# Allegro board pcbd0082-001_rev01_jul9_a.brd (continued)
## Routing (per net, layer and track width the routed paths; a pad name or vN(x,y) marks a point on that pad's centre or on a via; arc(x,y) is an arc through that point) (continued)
VDD_CORE_EN: length 29.2
  TOP w0.127: v3(30.09,33.65) 30.05,33.65 29.63,33.23 28.96,33.23 28.69,33.51
  TOP w0.147: 28.69,33.51 28.18,34.02 28.18,38 28.31,38.12 28.31,40.54 TP58.1 ; U10.6 30.73,20.47 30.66,20.4 30.2,20.4 v4(29.49,21.11)
  02_GND w0.127: v3(30.09,33.65) 30.46,33.28 U2.G13
  07_SIG w0.121: v3(30.09,33.65) 29.69,33.26 29.69,32.65 29.2,32.15 29.2,31.27 28.05,30.12 28.05,28.22 28.31,27.96 28.31,26.7 29.07,25.95 29.07,24.48 28.44,23.85 28.44,21.99 29.32,21.11 v4(29.49,21.11)
VDD_CORE_PGOOD: length 44.3
  TOP w0.132: U1.P28 v2(45.9,37.28) ; U1.N28 v2(45.9,36.28)
  TOP w0.147: U10.40 31.47,23.67 v4(31.36,23.56) 31.14,23.77 R87.1
  TOP w0.254: TP59.1 29.71,12.79 v5(29.83,12.91)
  02_GND w0.127: U2.E2 37.58,32.28 37.86,32 38.06,32 v3(38.6,31.47)
  07_SIG w0.121: v4(31.36,23.56) 33.17,23.56 34.22,24.6 34.22,25.23 34.59,25.6 34.59,28.05 34.64,28.1 34.64,29.73 35.29,30.38 37.58,30.38 38.6,31.39 v3(38.6,31.47) 38.99,31.86 45.29,31.86 46.47,33.04 46.47,35.71 45.9,36.28 v2(45.9,36.28) v2(45.9,37.28)
  08_SIG w0.121: v4(31.36,23.56) 31.36,20.85 30.69,20.19 30.69,17.37 30.59,17.27 30.59,13.68 v5(29.83,12.91)
VDDA_DDR0_32A: length 10
  TOP w0.254: v2(64.9,47.28) U1.AC10 ; v2(64.9,46.28) U1.AB10
  BOTTOM w0.254: v1(67.81,50.19) 67.4,49.79 67.4,48.77 66.41,47.78 C116.1 v2(64.9,47.28) 64.4,47.78 C187.1 ; U1.AC10 v2(64.9,46.28) U1.AB10 ; C44.1 v2(56.9,38.28)
  BOTTOM w0.508: L7.2 56.96,38.22 v2(56.9,38.28)
VDDA_DDR0_32B: length 7.1
  TOP w0.254: U1.Y10 v2(64.9,44.28) U1.AA10
  07_SIG w0.203: v2(64.9,44.28) 64.95,44.28 65.45,43.78 65.45,42.51 66.12,41.84 67.27,41.84 67.81,41.3 v8(67.9,41.28)
  BOTTOM w0.254: v2(64.9,44.28) U1.AA10
VDDA_PCIE0: length 13.7
  TOP w0.254: v2(62.9,50.28) U1.AF12 ; v2(60.9,50.28) U1.AF14 ; v2(61.9,50.28) U1.AF13
  BOTTOM w0.254: v2(64.9,54.28) 64.85,54.34 C279.1 64.85,55.48 66.28,56.92 67.3,56.92 v1(67.68,57.3) ; v2(60.9,50.28) C90.1 ; C170.1 63.4,49.78 C37.1 v2(62.9,50.28) C169.1 ; v2(61.9,50.28) C89.1 ; v2(63.9,53.28) 63.9,53.04 C278.1
  BOTTOM w0.381: v4(56.9,50.28) 56.9,50.33 56.97,50.4 56.97,50.56 57.69,51.28 v4(57.9,51.28)
VDDA_PLL: length 10.5
  TOP w0.254: v2(64.9,41.28) U1.U10 ; U1.M27 v2(46.9,35.28) ; U1.N27 v2(46.9,36.28) ; U1.AC18 v2(55.9,47.28) ; U1.K27 v2(46.9,33.28)
  BOTTOM w0.254: v2(46.9,36.28) C27.1 ; v2(46.9,33.28) C25.1 ; v2(55.9,47.28) C28.1 ; v2(46.9,35.28) C26.1 ; v1(42.91,28.22) 42.28,28.85 42.28,29.61 41.77,30.12 v4(40.75,30.12) ; v2(64.9,41.28) C29.1
  vias: v4(40.75,31.27)
VDDA_SERDES: length 23.3
  TOP w0.254: U1.AE24 v2(49.9,49.28) ; U1.AE23 v2(50.9,49.28) ; U1.AF23 v2(50.9,50.28) ; U1.AF22 v2(51.9,50.28) ; U1.AE22 v2(51.9,49.28)
  BOTTOM w0.203: v4(57.9,47.28) 58.27,46.91 58.35,46.91 58.5,46.77 59.1,46.77 59.38,46.48 59.38,46.42 59.42,46.38 v1(59.42,40.16)
  BOTTOM w0.254: v2(49.9,49.28) U1.AE24 C92.1 ; C94.1 51.41,47.78 51.4,47.78 ; v2(50.9,49.28) 51.4,48.78 51.4,47.78 ; C172.1 C93.1 51.4,47.78 ; U1.AF22 v2(51.9,49.28) ; v2(50.9,50.28) C40.1
  BOTTOM w0.457: v2(50.9,50.28) 50.9,50.33 50.79,50.44 50.79,51.84 C281.1
  BOTTOM w0.508: C280.1 51.93,53.24 51.23,52.53 C281.1 ; v4(57.9,47.28) v2(57.9,48.28)
VDDA_TS0: length 8.1
  TOP w0.254: U1.M32 v2(41.9,35.28)
  BOTTOM w0.127: L14.1 40.93,35.37 40.07,35.37 39.83,35.12 39.83,34.74 39.68,34.59 38.24,34.59 v1(37.74,34.09)
  BOTTOM w0.254: v2(41.9,35.28) 41.02,35.28 L14.1 ; v2(41.9,35.28) U1.M32 C86.1 ; v2(41.9,35.28) 42.4,34.78 C74.1
VDDAH_PCIE0: length 17.4
  TOP w0.254: v2(58.9,50.28) U1.AF16
  BOTTOM w0.254: L1.2 67.94,55.13 68.57,54.51 68.57,54 v1(67.93,53.36) 67.52,53.78 63.69,53.78 63.4,53.49 63.4,53.09 63.09,52.78 61.7,52.78 61.4,53.08 61.4,53.45 61.39,53.46 61.39,53.49 61.1,53.78 59.69,53.78 59.4,53.48 C39.1 C38.1 C91.1 v2(58.9,50.28) C30.1
VDDAH_SERDES: length 18.4
  TOP w0.254: U1.AF20 v2(53.9,50.28) ; U1.AF21 v2(52.9,50.28)
  BOTTOM w0.254: v2(53.9,50.28) U1.AF21 53.4,49.78 v2(52.9,50.28) ; v2(53.9,50.28) C102.1 C43.1 ; v2(53.9,50.28) 54.31,50.7 55.11,50.7 55.4,50.99 C101.1 C42.1 C41.1 55.4,54.48 55.1,54.78 55.09,54.78 54.72,55.14 54.72,56.28 54.09,56.92 53.71,56.92 53.2,56.41 52.77,56.41 52.44,56.74 52.44,56.74 52.39,56.79 51.29,56.79 v1(50.91,56.41) 50.33,56.99 50.33,57.1 L15.2
VDDQ_VTT_EN: length 70.5
  TOP w0.127: v3(33.87,33.55) 33.48,33.95 32.58,33.95 U2.H12
  TOP w0.147: TP65.1 88,21.07 v4(87.36,20.43) 86.85,19.92 86.85,19.2 86.45,18.79 U3.16 85.6,19.32 85.46,19.45 85.33,19.45 85.2,19.32 U3.17
  03_SIG w0.121: v5(82.66,23.14) 78.35,23.14 73.77,27.71 45.33,27.71 44.82,28.22 39.99,28.22 37.07,31.14 35.42,31.14 34.91,31.65 34.91,32.93 34.66,33.18 34.27,33.18 33.9,33.55 v3(33.87,33.55)
  07_SIG w0.121: v4(87.36,20.43) 86.95,20.02 86.04,20.02 85.98,19.96 84.32,19.96 83.3,20.98 83.3,22.5 v5(82.66,23.14)
VDDQ_VTT_PGOOD: length 59.8
  TOP w0.127: U2.E1 38.36,32.73 38.99,32.73 v3(39.41,33.15)
  TOP w0.147: U3.20 84,19.52 84.57,20.09 v4(84.57,20.43) 84.66,20.43 85.08,20.85 85.08,21.74 85.46,22.12 86.09,22.12 86.47,22.5 TP60.1
  03_SIG w0.121: v3(39.41,33.15) 40.78,31.77 41.01,31.77 42.15,30.63 44.71,30.63 44.73,30.65 45.07,30.65 45.09,30.63 45.33,30.63 46.2,29.76 72.23,29.76 77.58,24.41 v5(82.66,24.41)
  07_SIG w0.121: v5(82.66,24.41) 83.81,23.26 83.81,21.19 v4(84.57,20.43)
3N2284: length 4.1
  TOP w0.147: U14.1 35.05,49.82 34.79,49.55 v1(33.01,49.55) 32.3,49.55 32.16,49.7 R268.2
3N2285: length 1.2
  TOP w0.147: v4(36.44,56.12) 36.55,56 U14.11
3N2286: length 2.5
  TOP w0.147: U14.20 33.79,51.22 33.39,50.82 v1(33.08,50.82) R15.2
3N2287: length 3.5
  TOP w0.147: v1(38.56,56.12) R14.2 37.43,56.09 U14.10
3N2290: length 1.6
  TOP w0.147: v4(38.68,51.33) 37.79,52.22 U14.7
3N2291: length 1.4
  TOP w0.147: v4(38.68,52.47) 38.21,52.47 37.96,52.72 U14.8
3N2301: length 2.7
  TOP w0.147: U14.5 37.81,50.84 37.81,49.92 R135.1
  vias: v4(38.68,49.12)
3N2302: length 2.2
  TOP w0.147: U14.6 37.69,51.72 38.09,51.33 38.09,50.79 v4(38.68,50.19)
3N2521: length 11.3
  TOP w0.147: U15.7 v4(24.68,40.66) 25.13,41.12 R21.2
  BOTTOM w0.147: v1(25.95,31.95) 25.72,31.95 25.13,32.54 U7.7 25.13,36.09 24.52,36.7 24.52,40.51 v4(24.68,40.66)
6N3961: length 5.4
  TOP w0.132: v2(67.9,37.28) U1.P7
  BOTTOM w0.147: R124.2 69.96,34.83 R272.1 69.08,35.72 v1(69.08,36.85) 68.65,37.28 v2(67.9,37.28)
6N3963: length 2.9
  TOP w0.132: v2(65.9,37.28) U1.P9
  BOTTOM w0.147: v1(64.9,38.28) 65.48,37.58 65.61,37.58 v2(65.9,37.28) R310.1
6N4748: length 2.8
  TOP w0.147: R7.2 R8.2 79.41,30.67 v1(78.55,30.67) C105.1
9N1879: length 2.5
  TOP w0.147: U2.A4 36.41,29.64 v3(35.85,29.08)
  BOTTOM w0.147: v3(35.85,29.08) 35.67,29.26 R264.1
9N2032: length 3.7
  TOP w0.147: v7(27.67,24.66) 27.6,24.74 U12.15
  BOTTOM w0.147: v7(27.67,24.66) 27.04,25.3 27.04,26.44 26.4,27.07 R59.1
9N2141: length 8.9
  TOP w0.147: DS1.2 10.45,57.99 v5(11.04,58.57) v1(11.04,59.84)
  BOTTOM w0.147: R277.2 11.04,57.39 v5(11.04,58.57)
9N2152: length 8.4
  TOP w0.147: DS1.3 11.95,57.68 12.18,57.91 v6(12.18,58.57)
  BOTTOM w0.147: v6(12.18,58.57) 12.18,57.64 R276.2
10N2223: length 3.1
  BOTTOM w0.147: v1(45.2,17.42) 45.71,17.93 46.09,17.93 46.68,18.53 R117.1
  BOTTOM w0.508: C46.1 R117.1
10N2224: length 5.6
  BOTTOM w0.147: v1(65.38,23.36) 65.38,22.24 64.94,21.8 64.94,21.18 65.83,20.29 65.83,20.16 66.28,19.7 C47.1
  BOTTOM w0.508: C47.1 R116.1
10N2225: length 9.1
  BOTTOM w0.132: U5.3 50.13,21.79 50.69,22.35 50.69,23.88 50.46,24.1 50.46,24.22 50.41,24.28 50.41,25.55 50.11,25.85 49.72,25.85 49.33,26.23 49.33,26.46 49.08,26.72 47.64,26.72 v1(46.98,26.06)
10N2227: length 3.1
  BOTTOM w0.147: v1(70.85,23.4) 70.85,23.32 70.99,23.19 70.99,22.38 70.72,22.11 70.34,22.11 69.73,21.51 U6.3
10N2228: length 3.8
  BOTTOM w0.147: C32.2 73.81,24.06 74.03,24.28 v1(75.17,24.28) 76.02,24.28 R119.1
10N2229: length 7.8
  BOTTOM w0.147: v1(75.17,25.68) 74.22,24.72 72.72,24.72 72.46,24.47 72.46,24.22 72.21,23.97 C32.1 72.12,23.26 71.26,22.41 71.26,22.26 70.84,21.84 70.45,21.84 70.23,21.62 U6.4
10N2230: length 9
  BOTTOM w0.147: v1(65.77,27.17) 65.41,26.81 65.41,26.05 65.65,25.8 66.15,25.8 66.4,25.56 R170.2 66.41,24.77 66.41,23.01 67.3,22.12 67.3,20.22 67.58,19.93 U6.39
10N2232: length 7.8
  TOP w0.147: v1(46.22,21.36) 46.34,21.49 46.85,21.49 47.49,22.12 v5(51.13,22.12)
  BOTTOM w0.147: C33.1 51.35,22.34 v5(51.13,22.12) 50.63,21.63 U5.4
10N2233: length 10.9
  BOTTOM w0.147: R118.1 C33.2 52.95,23.39 52.34,24 52.34,26.47 51.97,26.84 49.72,26.84 49.34,27.22 49.34,27.47 49.08,27.72 47.5,27.72 47.1,27.33 v1(46.98,27.33)
10N2235: length 7.4
  BOTTOM w0.147: R169.2 v1(44.82,22.12) 45.45,22.12 46.22,22.88 47.1,22.88 47.61,22.38 47.61,20.22 47.89,19.93 U5.39
10N2253: length 3.1
  BOTTOM w0.147: v1(67,23.26) 67.55,22.72 R126.2 68.06,22.63 68.22,22.47 68.22,21.83 68.73,21.32 U6.1
10N2256: length 3.3
  BOTTOM w0.147: U5.1 49.13,21.32 48.46,21.99 R74.2 48.16,22.72 v1(47.36,23.52)
10N2259: length 9.6
  BOTTOM w0.147: v1(58.79,21.49) 58.44,21.83 58.44,22.89 57.93,23.41 R118.2 55.11,22.63 52.65,22.63 52.53,22.5 52.53,21.87 52.13,21.47 U5.7
10N2262: length 8
  BOTTOM w0.147: R119.2 77.37,23.01 v1(75.17,23.01) 74.79,22.63 72.3,22.63 72.17,22.5 72.17,21.93 72.12,21.89 72.12,21.87 71.73,21.47 U6.7
10N2370: length 11.7
  TOP w0.203: 38.15,23.71 37.42,22.97 U10.30
  TOP w0.508: R401.2 40.88,19.72 R402.2 41.26,20.1 C143.1 41.26,24.13 40.5,24.89 39.63,24.89 v1(39.61,24.87) 39.23,24.53 39.22,24.53 38.81,24.12 C124.1 38.34,23.9 38.15,23.71
10N2381: length 3.8
  TOP w0.147: U10.19 36.03,17.3 36.15,17.17 37.15,17.17 38.09,16.23 v4(38.09,16.22)
  BOTTOM w0.147: v1(37.58,15.64) 38.09,16.15 v4(38.09,16.22)
10N2383: length 5.9
  TOP w0.147: v1(27.74,13.26) 28.1,13.61 29.07,13.61 29.32,13.87 29.32,15.26 29.74,15.68 C81.1 R120.1 30.9,15.86 R326.2
10N2384: length 11.6
  TOP w0.147: C48.1 31.86,15.02 v4(32.71,15.87) C52.1 33.28,16.46 33.5,16.46 33.75,16.71 33.75,16.73 33.77,16.75 33.77,17.1 33.75,17.12 33.75,17.19 33.53,17.41 U10.14
  BOTTOM w0.147: v4(32.71,15.87) 32.71,15.51 32.76,15.46 32.76,14.87 33.26,14.37 35.29,14.37 35.6,14.68 35.6,14.71 35.72,14.83 35.75,14.83 35.93,15.01 35.93,17.68 v1(36.18,17.93)
10N2385: length 4.3
  TOP w0.147: R182.1 34.02,15.3 v4(33.64,14.92)
  BOTTOM w0.147: v1(33.64,17.93) 33.9,17.68 33.9,16.28 33.64,16.03 v4(33.64,14.92)
10N2386: length 2
  TOP w0.147: v1(31.86,12.98) C48.2 R328.1
10N2397: length 4.9
  TOP w0.147: U10.11 31.46,17.78 31.43,17.75 v5(31.17,17.75) 30.76,17.22 R3.2
  BOTTOM w0.147: v1(32.25,20.09) 31.36,19.2 31.36,18.06 31.17,17.87 v5(31.17,17.75)
10N2399: length 4.2
  TOP w0.147: U10.10 31.14,18.47 30.98,18.31 30.98,18.21 30.7,17.93 30.63,17.93 v4(30.25,17.55)
  BOTTOM w0.147: v4(30.25,17.55) 30.47,17.55 30.71,17.79 30.71,17.94 30.98,18.2 v1(30.98,19.84)
10N2403: length 5.4
  TOP w0.147: U10.26 38.43,20.97 v4(39.06,21.61)
  BOTTOM w0.147: v1(41.26,21.11) 41.26,21.77 41.11,21.92 40.38,21.92 40.12,22.18 39.63,22.18 v4(39.06,21.61)
10N2407: length 5.3
  TOP w0.147: R312.2 26.57,16.22 C144.1 26.56,16.53 v1(28.69,16.53) 29.79,16.53 R3.1
10N2409: length 3.9
  TOP w0.147: U10.27 38.2,21.47 38.53,21.81 38.53,21.99 39.04,22.5 v4(39.06,22.63)
  BOTTOM w0.147: v4(39.06,22.63) v1(40.5,22.63)
10N2410: length 13.2
  TOP w0.147: v5(35.36,13.74) 35.36,14.4 R287.2
  07_SIG w0.121: v4(38.89,20.72) 38.89,20.25 38.59,19.96 38.16,19.96 37.9,19.7 37.9,18.25 38.47,17.68 38.47,16.91 38.99,16.39 v4(38.99,16.28)
  BOTTOM w0.147: v5(35.36,13.74) 35.36,13.17 35.55,12.98 37.2,12.98 37.33,13.1 37.33,14.76 37.58,15.01 38.21,15.01 38.52,15.32 38.52,15.81 v4(38.99,16.28)
10N2411: length 1.3
  TOP w0.147: v4(30.25,18.44) 30.79,18.97 U10.9
10N2412: length 5.4
  TOP w0.147: U10.1 30.56,22.97 v5(30.47,23.05)
  BOTTOM w0.254: v4(27.42,21.23) 27.42,21.74 29.2,23.52 30,23.52 v5(30.47,23.05)
10N2498: length 5.3
  TOP w0.147: v1(28.69,15.26) 28.69,15.64 29.25,16.21 31.11,16.21 31.6,16.7 R326.1 32.21,17.17 32.25,17.17 32.53,17.45 U10.12
10N2504: length 11.9
  TOP w0.147: R120.2 30.65,14.77 30.65,12.54 31.19,12 v1(32.97,12) R313.1 33.01,13.14 33.01,13.49 33.6,14.08 C49.1 32.8,14.92 R328.2 33.55,15.72 C52.2 34.03,16.37 34.03,16.62 34.04,16.63 34.04,17.22 34.03,17.23 34.03,17.42 34.03,17.42 U10.15
10N2528: length 10.7
  TOP w0.147: R13.2 36.4,14.58 C34.1 C35.1 ; v4(39.06,18.95) R324.1 ; C35.1 36.12,16.51 35.9,16.51 35.68,16.73 35.47,16.73 35.03,17.18 U10.17 ; C35.1 v4(36.4,16.28)
  BOTTOM w0.147: v4(36.4,16.28) 37.07,16.28 37.46,16.67 38.22,16.67 38.72,17.17 38.72,18.6 v4(39.06,18.95) 39.23,18.95 v1(39.87,18.31)
10N2535: length 5.7
  TOP w0.147: v4(35.42,15.3) 35.33,15.39 C50.1 34.53,17.08 U10.16
  BOTTOM w0.147: v4(35.42,15.3) 35.42,17.42 v1(34.91,17.93)
11N1937: length 5.9
  TOP w0.203: U9.5 17.64,18.95 17.74,18.85 17.74,18.72 17.89,18.57 17.89,18.49
  TOP w0.254: L19.2 16.64,13.37 16.46,13.19 v1(16.46,12.13)
  TOP w0.381: 17.89,18.49 17.89,17.17 17.51,16.79
  TOP w0.508: 17.51,16.79 17.51,16.78 17.2,16.46
11N1952: length 3.2
  TOP w0.147: L21.1 v4(62.09,9.04)
  TOP w0.254: C127.2 66.15,11.8 65.9,11.55 65.9,10.88 65.91,10.87 U13.12
11N1953: length 4.5
  TOP w0.147: R113.2 v4(69.68,11.8) 69.33,11.8 R112.1 68.46,10.93 68.46,8.57 68.19,8.29 U13.5
11N1966: length 21.8
  TOP w0.147: v5(22.09,21.99) 21.9,22.18 20.51,22.18 20.35,22.34 20.34,22.34 20.27,22.41 U9.16 ; R104.1 v7(8.24,23.52)
  07_SIG w0.121: v5(22.09,21.99) 22.09,21.36 21.32,20.6 20.43,20.6 19.55,21.49 19.55,23.81 18.32,25.03 16.13,25.03 15.07,23.97 11.61,23.97 11.55,23.91 10.81,23.91 10.69,23.79 8.51,23.79 v7(8.24,23.52)
11N1968: length 5.1
  TOP w0.254: v1(13.9,12.14) 13.9,13.24 14.16,13.49
  TOP w0.381: 15.62,19.47 15.11,19.47 14.47,18.82 14.47,17.17 14.08,16.79
11N1970: length 2.8
  TOP w0.381: 14.97,26.19 14.97,24.28 15.5,23.76 15.62,23.76
  vias: v1(14.08,27.07)
11N1971: length 6.4
  TOP w0.381: 19.73,19.47 20.25,19.47 21.22,18.49 21.22,16.89
  TOP w0.508: v1(22.72,13.74) 22.09,13.74 21.81,14.02 L12.1
11N1979: length 23.8
  TOP w0.147: R98.1 v5(7.35,23.52) ; U9.12 20.53,20.81 20.66,20.94 23.14,20.94 v7(23.36,20.72)
  07_SIG w0.121: v7(23.36,20.72) 22.47,20.72 21.96,20.22 20.31,20.22 19.16,21.36 19.16,23.52 18.91,23.77 15.74,23.77 15.54,23.58 10.83,23.58 10.79,23.54 9.4,23.54 8.94,23.08 7.79,23.08 v5(7.35,23.52)
11N1981: length 2.6
  TOP w0.147: v4(66.66,12.64) 67.22,12.07 67.22,11.54 66.91,11.23 U13.10
11N2138: length 2.2
  TOP w0.147: U3.19 84.4,19.41 84.95,19.96 84.99,19.96 v4(85.59,20.43)
11N2140: length 3.6
  TOP w0.147: R107.2 86.08,20.04 86.03,20.04 85.96,19.96 85.43,19.96 85.17,19.76 84.8,19.38 U3.18
  BOTTOM w0.147: v4(86.47,20.48) v1(86.47,21.36)
11N2146: length 4.4
  TOP w0.147: U3.8 84.8,14.77 v4(84.78,14.76) R127.1
  BOTTOM w0.147: R4.2 86.09,16.52 C31.1 85.6,15.57 v4(84.78,14.76)
11N2152: length 4.1
  TOP w0.147: R127.2 83.3,14.92 83.3,15.52 83.58,15.8 U3.6
  BOTTOM w0.147: C128.1 83.85,15.52 v4(83.08,14.76) 83.08,14.72 v1(83.68,14.12)
11N2159: length 7.9
  TOP w0.147: v5(87.15,15.9) 86.98,16.06 86.98,16.79 86.87,16.9 U3.12
  BOTTOM w0.147: R331.2 87.36,18.69 87.74,18.31 v1(87.74,16.91) 87.74,16.5 v5(87.15,15.9) 87.15,14.88 C205.1
11N2173: length 12.5
  TOP w0.147: v7(88.51,9.29) 88.13,8.91 86.86,8.91 86.67,9.1 Q1.3 ; U3.14 86.91,17.7 87.02,17.8 v5(87.15,17.8)
  08_SIG w0.121: v5(87.15,17.8) 88.51,16.44 v7(88.51,9.29)
11N2175: length 11.5
  TOP w0.147: Q1.4 87.92,9.6 89.78,11.45 v1(89.78,15.01) 88.82,15.01 88.63,15.2 88.63,15.2 C129.2 87.26,16.58 87.26,17.04 87,17.3 U3.13
11N2177: length 6
  TOP w0.147: Q1.5 87.95,12.8 88.63,13.49 v1(88.63,14.37) 87.62,15.39 86.86,15.39 86.3,15.95 U3.11
11N2179: length 4.1
  TOP w0.147: U3.15 86.64,18.1 87.11,18.57 87.11,19.07 87.62,19.58 v1(88.25,19.58) 88.25,18.95 87.91,18.6 R108.1
11N2181: length 3.1
  TOP w0.147: R108.2 88.01,17.93 v1(88.89,17.93) 88.89,17.04 88.67,16.83 C129.1
11N2191: length 13.1
  TOP w0.147: U3.9 85.2,15.27 85.33,15.14 86.6,15.14 87.36,14.37 v7(87.62,14.37)
  08_SIG w0.121: v7(87.62,14.37) 86.09,15.9 86.09,18.18 85.08,19.2 85.08,21.99 84.35,22.72 v4(84.32,22.72)
11N2199: length 5.6
  TOP w0.147: R337.1 84.61,21.99 84.32,21.99 83.55,21.23 v1(83.55,20.72) 83.55,18.95 83.3,18.69 U3.1
11N2202: length 6.5
  TOP w0.147: U3.5 83.01,16.5 82.79,16.28 v5(82.79,15.77)
  BOTTOM w0.147: C165.1 83.17,16.15 v5(82.79,15.77) 82.63,15.61 82.63,14.57 82.79,14.4 82.79,14.25 83.1,13.94 83.1,13.88 83.62,13.36 v1(84.82,13.36)
11N2253:
  vias: v1(86.35,13.99)
11N2258: length 0.9
  TOP w0.508: v4(83.93,11.97) 83.93,11.11 C51.1
11N2296: length 3.6
  TOP w0.381: 19.42,26.39 19.42,24.32
  TOP w0.508: v1(17.64,27.33) 18.86,27.33 L20.1
12N2312: length 6.8
  TOP w0.147: v3(83.41,51.33) 83.41,50.3 82.66,49.55 R189.2
  BOTTOM w0.147: v3(83.41,51.33) v1(83.41,48.3)
  BOTTOM w0.254: U17.L8 v3(83.41,51.33)
12N3057: length 5.4
  TOP w0.147: v3(83.41,39.77) 83.41,39.28 83.17,39.04 83.17,38.87 82.81,38.5 82.7,38.5 R352.2
  BOTTOM w0.147: v3(83.41,39.77) v1(83.41,36.87)
  BOTTOM w0.254: U18.L8 v3(83.41,39.77)
12N3220: length 4.9
  TOP w0.147: R353.2 83.3,27.51 83.41,27.62 v3(83.41,28.21)
  BOTTOM w0.147: v3(83.41,28.21) v1(83.41,25.44)
  BOTTOM w0.254: U19.L8 v3(83.41,28.21)
12N3291: length 6.6
  TOP w0.147: v3(77.01,33.01) 77.01,33.01 R340.1
  BOTTOM w0.147: v1(72.76,31.77) 77.2,31.77 77.41,31.98 U19.D3
  BOTTOM w0.254: U19.D3 v3(77.01,33.01)
12N3293: length 6.3
  TOP w0.147: v3(75.41,29.01) 75.43,29.02 75.43,31.3 R338.1
  BOTTOM w0.147: v3(75.41,29.01) v1(73.01,28.98)
  BOTTOM w0.254: U19.B7 v3(75.41,29.01)
12N3294: length 7.1
  TOP w0.147: v3(76.21,29.01) 76.21,29.11 75.86,29.47 75.86,30.56 76.31,31.01 R339.2
  BOTTOM w0.147: v1(73.01,30.25) 76.19,30.25 76.61,29.82 U19.C7
  BOTTOM w0.254: U19.C7 v3(76.21,29.01)
13N4315: length 3.2
  TOP w0.147: v1(22.89,58.53) R371.1 23.52,56.79 23.86,56.79 24.26,56.39 U20.15
13N4321: length 5.4
  TOP w0.147: R393.1 22.83,52.72 22.14,52.02 22.14,51 v1(21.83,50.7)
  TOP w0.254: U20.1 23.23,54.64 23.1,54.51 C282.1 22.76,53.74 R372.1 22.85,53.58 R393.1
13N4347: length 8
  BOTTOM w0.147: U21.15 6.95,46.61 7.61,47.27 7.61,47.77 7.55,47.82 7.55,47.84 7.41,47.98 7.41,47.99 7.3,48.1 7.27,48.1 7.22,48.16 6.46,48.16 6.3,48.32 R375.1 6.3,49.09 5.53,49.86 3.49,49.86 v1(2.91,50.44)
13N4351: length 9.2
  BOTTOM w0.147: v1(6.08,38.5) 6.59,39.01 6.59,40.03 6.34,40.28 6.34,41.43 6.71,41.79 R394.1
  BOTTOM w0.254: R394.1 R376.1 7.73,43.46 7.4,43.79 U21.1 8.3,44.86 C283.1
_NFP_ARM_SPI_FLASH_MOSI: length 2.4
  TOP w0.132: U1.U31 v8(42.9,41.28)
  BOTTOM w0.147: v8(42.9,41.28) 42.03,40.41 R201.1
_NFP_ARM_SPI_FLASH_SCK: length 5.6
  TOP w0.132: U1.R29 v2(44.9,38.28)
  BOTTOM w0.147: v2(44.9,38.28) 44.46,37.84 44.46,37.22 44.08,36.84 42.42,36.84 v1(42.15,37.11) 41.9,36.85 R204.1
_NFP_ARM_SPI_FLASH_SEL: length 0.7
  TOP w0.132: U1.U32 v3(41.9,41.28)
_NFP_CFG_SPI_FLASH_MOSI: length 4.2
  TOP w0.132: U1.U30 v8(43.9,41.28)
  BOTTOM w0.147: v8(43.9,41.28) 42.4,39.78 41.4,39.78 41.17,39.56 R202.1
_NFP_CFG_SPI_FLASH_SCK: length 3
  TOP w0.132: U1.T31 v8(42.9,39.28)
  BOTTOM w0.147: v8(42.9,39.28) 42.4,38.78 42.3,38.78 41.26,37.74 R205.1
_NFP_CFG_SPI_FLASH_SEL: length 1.7
  TOP w0.132: U1.T32 v2(41.9,39.28)
  BOTTOM w0.147: v2(41.9,39.28) 41.25,38.63 R281.1
_NFP_CLK_NRESET_L: length 3.7
  TOP w0.147: v3(30.09,36.17) v1(29.25,36.17)
  02_GND w0.121: U2.M13 30.48,35.78 v3(30.09,36.17)
  BOTTOM w0.147: v3(30.09,36.17) 29.58,36.17 29.57,36.18 R410.1
_NFP_CORE_VID0: length 7.2
  TOP w0.147: U10.38 33.03,24.07 32.5,24.6 32.38,24.6 32.38,24.61 31.68,24.61 31.67,24.6 31.29,24.6 31.29,24.61 31.03,24.61 v5(30.59,25.04) R83.2 R84.1
  BOTTOM w0.147: R84.1 29.71,25.3 29.96,25.04 v5(30.59,25.04) v1(30.59,24.15)
_NFP_CORE_VID1: length 6.1
  TOP w0.147: R92.1 v5(31.48,25.06) 31.5,25.04 32.63,25.04 33.53,24.14 U10.37
  BOTTOM w0.147: v1(32.12,24.41) 31.48,25.04 v5(31.48,25.06) R92.1 R97.2
_NFP_CORE_VID2: length 5.3
  TOP w0.147: U10.36 34.03,24.4 v7(33.64,24.79) 33.64,25.39 R96.2 R93.1
  BOTTOM w0.147: v7(33.64,24.79) 32.82,24.79 32.5,25.11 32.37,25.24 R93.1
_NFP_CORE_VID3: length 4.4
  TOP w0.147: U10.35 34.53,24.66 v7(34.66,24.79) 34.15,25.3 R94.1
  BOTTOM w0.147: R95.2 R94.1 v7(34.66,24.79)
_NFP_CORE_VID4: length 5
  TOP w0.147: U10.34 35.03,24.52 35.19,24.69 35.58,24.69 v7(35.67,24.79) 35.52,25.03 35.38,25.17 35.17,25.17 35.04,25.3 R90.1 R91.2
  BOTTOM w0.147: R90.1 v7(35.67,24.79)
_NFP_CORE_VID5: length 4.8
  TOP w0.147: U10.33 35.53,24.06 35.8,24.33 35.86,24.33 36.32,24.79 v7(36.69,24.79) 36.82,24.92 R77.1
  BOTTOM w0.147: v7(36.69,24.79) 36.82,25.17 R77.1 R82.2
_NFP_CORE_VID6: length 5.2
  TOP w0.147: U10.32 36.03,24.11 36.2,24.28 37.2,24.28 v7(37.71,24.79) R78.1 R80.2
  BOTTOM w0.147: R78.1 v7(37.71,24.79)
_NFP_CORE_VID7: length 6.5
  TOP w0.147: R79.1 39.48,25.8 v5(38.72,25.04) 37.58,23.9 36.67,23.9 36.53,23.75 U10.31
  BOTTOM w0.147: R81.2 v5(38.72,25.04) ; v5(38.72,25.04) v1(38.72,24.15) ; v5(38.72,25.04) 38.94,25.04 R178.2
_NFP_JTAG_ARM_TDO: length 16.7
  TOP w0.132: U1.Y30 v2(43.9,44.28)
  04_SIG w0.121: v2(43.9,44.28) 43.87,44.28 43.42,43.84 41.14,43.84 39.93,45.05 39.93,45.14 37.68,47.39 34.68,47.39 34.56,47.27 34.4,47.27 31.99,44.85 v7(30.63,44.85)
_NFP_PCIE0_PER0_N: length 6.4
  TOP w0.139: v8(62.9,54.28) U1.AK12
  07_SIG w0.11: v4(66.38,57.59) 66.24,57.46 66.24,55.94 64.98,54.69 63.73,54.69 63.72,54.68 63.29,54.68 v8(62.9,54.28)
_NFP_PCIE0_PER0_P: length 6.4
  TOP w0.139: v2(62.9,55.28) U1.AL12
  07_SIG w0.11: v2(62.9,55.28) 62.9,55.09 63.11,54.89 63.64,54.89 63.64,54.9 64.89,54.9 66.03,56.03 66.03,56.98 65.91,57.1 65.88,57.1 v4(65.38,57.59)
_NFP_PCIE0_PER1_N: length 5.1
  TOP w0.139: U1.AL13 61.85,55.24 61.85,56.32 62,56.47 62.46,56.47 62.72,56.72 64.05,56.72 64.38,57.05 v4(64.38,57.59)
_NFP_PCIE0_PER1_P: length 5.1
  TOP w0.139: v4(63.47,57.59) 63.47,57.61 63.47,57.92 63.57,58.02 63.78,58.02 63.92,57.88 63.92,57.4 64.02,57.31 64.02,57.13 63.87,56.98 62.61,56.98 62.36,56.72 61.9,56.72 61.4,56.23 U1.AM13
_NFP_PCIE0_PER2_N: length 7
  TOP w0.139: v2(59.9,54.28) U1.AK14
  07_SIG w0.106: 60.17,57.01 60.13,57.01 60.12,57.02 59.78,57.02 59.6,57.02 59.45,56.86 59.45,56.86 59.3,56.7 59.3,54.89 v2(59.9,54.28)
  07_SIG w0.11: 60.17,57.01 61.75,57.01 61.94,57.2 61.94,57.47 61.82,57.59 v4(61.55,57.59)
_NFP_PCIE0_PER2_P: length 6.9
  TOP w0.139: v2(59.9,55.28) U1.AL14
  07_SIG w0.106: v2(59.9,55.28) 59.9,54.91 59.8,54.81 59.67,54.81 59.5,54.97 59.5,56.62 59.69,56.81 60.03,56.81 60.04,56.8 60.08,56.8 60.09,56.8 60.15,56.8 60.15,56.8 60.17,56.8
  07_SIG w0.11: v4(62.54,57.59) 62.27,57.59 62.15,57.47 62.15,57.11 61.84,56.79 61.66,56.79 61.66,56.8 60.17,56.8
_NFP_PCIE0_PER3_N: length 3.2
  TOP w0.139: v4(59.55,57.59) 59.27,57.32 58.94,56.99 58.94,55.59 59.4,55.14 U1.AL15
_NFP_PCIE0_PER3_P: length 3.4
  TOP w0.139: U1.AM15 59.4,55.83 59.2,56.03 59.2,56.88 59.45,57.14 59.74,57.14 60,57.4 60,57.76 60.14,57.9 60.35,57.9 60.44,57.81 60.44,57.72 v4(60.57,57.59)
_NFP_PCIE0_PER4_N: length 4.5
  TOP w0.139: v8(57.9,54.28) U1.AK16
  07_SIG w0.106: v8(57.9,54.28) 58.5,54.89 58.5,56.74 58.23,57.01 58.23,57.23 v4(58.6,57.59)
_NFP_PCIE0_PER4_P: length 4.5
  TOP w0.139: v2(57.9,55.28) U1.AL16
  07_SIG w0.106: v2(57.9,55.28) 57.88,55.26 57.88,54.91 57.95,54.84 58.1,54.84 58.3,55.03 58.3,56.65 58.03,56.92 58.03,57.21 v4(57.65,57.59)
_NFP_PCIE0_PER5_N: length 3.5
  TOP w0.139: v4(55.65,57.59) 55.87,57.37 55.87,56.96 56.94,55.88 56.94,55.59 57.39,55.14 57.39,54.79 U1.AL17
_NFP_PCIE0_PER5_P: length 3.6
  TOP w0.139: U1.AM17 57.11,56.07 56.12,57.06 56.12,57.92 56.23,58.03 56.54,58.03 56.65,57.92 56.65,57.61 v4(56.63,57.59)
_NFP_PCIE0_PER6_N: length 5.2
  TOP w0.139: U1.AK18 v2(55.9,54.28)
  07_SIG w0.106: v4(53.64,57.59) 54.01,57.22 54.01,56.96 54.67,56.3 55.03,56.3 55.3,56.03 55.3,54.89 v2(55.9,54.28)
_NFP_PCIE0_PER6_P: length 5.1
  TOP w0.139: U1.AL18 v2(55.9,55.28)
  07_SIG w0.106: v2(55.9,55.28) 55.9,54.92 55.8,54.82 55.65,54.82 55.5,54.97 55.5,56.12 55.11,56.51 54.76,56.51 54.22,57.05 54.22,57.18 v4(54.63,57.59)
_NFP_PCIE0_PER7_N: length 6.1
  TOP w0.139: v4(51.42,57.59) 51.42,57.43 52.52,56.33 52.57,56.33 52.65,56.24 53.24,56.24 53.46,56.46 53.46,56.47 53.72,56.72 54.16,56.72 54.85,56.03 54.85,55.27 55.34,54.78 U1.AL19
_NFP_PCIE0_PER7_P: length 6
  TOP w0.139: v4(52.57,57.59) 52.25,57.91 52.04,57.91 51.9,57.76 51.9,57.31 52.63,56.58 52.67,56.58 52.76,56.5 53.13,56.5 53.2,56.56 53.2,56.57 53.61,56.98 54.26,56.98 55.11,56.13 55.11,55.93 55.26,55.78 U1.AM19
_NFP_PCIE0_RESET_OUT_L: length 11.7
  TOP w0.147: U1.N30 v2(43.9,36.28)
  BOTTOM w0.147: 45.4,35.16 45.02,34.78 R365.1 ; 45.4,35.16 R409.1 44.77,36.78 44.27,36.28 v2(43.9,36.28) ; 45.4,35.16 45.46,35.1 45.46,35.1 45.77,34.78 48.29,34.78 48.4,34.67 48.4,33.07 48.11,32.78 47.48,32.78 v1(46.98,32.28)
_NFP_SPI2_MOSI: length 1.8
  TOP w0.132: U1.U29 v8(44.9,41.28)
  BOTTOM w0.147: v8(44.9,41.28) 44.82,41.2 R203.1
_NFP_SPI2_SCK: length 6.8
  TOP w0.132: U1.T29 v2(44.9,39.28)
  08_SIG w0.121: v2(44.9,39.28) 45.33,38.86 45.33,34.86 v2(45.9,34.28)
  BOTTOM w0.147: R199.1 v2(45.9,34.28)
_NFP_UART_SR_TX: length 18.7
  TOP w0.132: U1.N32 v2(41.9,36.28)
  03_SIG w0.121: v2(41.9,36.28) 41.83,36.28 40.66,35.11 40.66,34.78 40.61,34.73 40.61,34.66 40.38,34.43 40.06,34.43 39.8,34.68 38.21,34.68 38.11,34.79 31.96,34.79 30.35,33.18 29.08,33.18 28.69,32.79 28.69,31.62 27.96,30.88 v12(27.33,30.88)
_PGRM_JTAG_TDO: length 16.6
  TOP w0.132: U1.AC32 v2(41.9,47.28)
  TOP w0.147: R262.1 v7(31.48,48.41)
  04_SIG w0.121: v2(41.9,47.28) 41.39,47.79 41.39,48.44 40.75,49.08 40.75,49.3 40.57,49.49 39.96,49.49 39.63,49.82 39.63,50.58 39.49,50.72 39.49,51.3 39,51.79 38.13,51.79 36.79,50.44 34.32,50.44 34.2,50.32 33.01,50.32 31.48,48.79 v7(31.48,48.41)
_PSU_I2C_SCL: length 17.8
  TOP w0.132: U1.AB29 v2(44.9,46.28)
  TOP w0.147: R138.1 v4(31.48,47.27)
  04_SIG w0.121: v2(44.9,46.28) 43.47,44.85 41.18,44.85 40.67,45.36 40.67,45.46 37.34,48.79 36.75,48.79 36.7,48.85 35.92,48.85 35.86,48.79 34.79,48.79 33.26,47.27 v4(31.48,47.27)
_PSU_I2C_SDA: length 20.7
  TOP w0.132: U1.AB28 v2(45.9,46.28)
  04_SIG w0.121: v4(30.72,46) 30.63,46.09 30.63,47.04 31.3,47.71 31.42,47.71 31.44,47.72 31.77,47.72 31.82,47.77 33.05,47.77 33.62,48.34 33.62,48.85 34.07,49.29 35.66,49.29 35.71,49.35 36.91,49.35 36.96,49.29 37.55,49.29 41.1,45.74 42.02,45.74 42.41,46.12 42.41,46.51 42.66,46.76 45.45,46.76 45.9,46.31 v2(45.9,46.28)
_SW1: length 2.1
  TOP w0.147: U10.25 v7(38.07,20.47) 38.43,20.47 R314.1
_SW2: length 4
  TOP w0.147: U10.24 38.08,19.97 v7(38.34,19.52) 38.34,17.89 R315.1
A_AZQ: length 5.2
  TOP w0.132: v2(65.9,45.28) U1.AA9
  07_SIG w0.127: v2(65.9,45.28) 65.9,45.11 66.28,44.73 66.28,43.9 v8(67.9,42.28)
  BOTTOM w0.254: v2(65.9,45.28) 65.4,45.78 R188.2
A_DZQ0: length 2.4
  TOP w0.132: v2(64.9,36.28) U1.N10
  BOTTOM w0.147: R187.2 v2(64.9,36.28) v1(64.9,35.34)
A_DZQ1: length 2.3
  TOP w0.132: v2(64.9,33.28) U1.K10
  BOTTOM w0.147: v1(64.9,32.42) v2(64.9,33.28) R186.2
CNTRL_SPI_CS: length 47
  02_GND w0.127: v3(38.6,35.08) 38.3,34.78 U2.K2
  07_SIG w0.121: v4(27.29,9.87) 29.13,9.87 29.57,10.31 31.28,10.31 31.79,9.8 v5(35.04,9.8) 35.28,9.56 41.38,9.56 41.52,9.42 43.29,9.42 v4(44.06,10.18)
  08_SIG w0.121: v3(38.6,35.08) 38.21,34.69 38.21,34.16 38.2,34.15 38.2,30.34 38.21,30.33 38.21,30.12 39.1,29.23 39.1,27.96 39.04,27.9 39.04,27.4 38.68,27.05 38.41,27.05 38.15,26.79 38.15,26.42 38.21,26.36 38.21,24.28 36.94,23.01 36.94,21.03 36.88,20.97 36.88,20.39 36.65,20.16 36.65,19.62 35.51,18.48 35.51,18.27 35.51,17.86 35.51,17.08 35.55,17.04 35.55,15.9 35.93,15.52 35.93,10.69 v5(35.04,9.8)
CNTRL_SPI_MISO: length 54.2
  TOP w0.147: v3(36.31,34.36) 36.4,34.28 U2.J3
  03_SIG w0.121: v5(32.5,11.07) 40.88,11.07 41.52,10.44 41.9,10.44 v4(42.15,10.18) 41.9,9.93 40.88,9.93 40.12,10.69 39.09,10.69 38.52,10.12 37.64,10.12 37.07,10.69 33.01,10.69 32.63,10.31 26.47,10.31 v4(26.02,9.87)
  08_SIG w0.121: v5(32.5,11.07) 31.99,11.58 31.99,17.68 33.64,19.33 33.64,19.52 34.07,19.95 34.2,19.95 34.91,20.66 34.91,22.38 36.18,23.65 36.18,25.42 37.26,26.5 37.26,27.84 37.11,27.99 37.11,33.7 36.45,34.36 v3(36.31,34.36)
CNTRL_SPI_MOSI: length 49.2
  TOP w0.127: v3(39.41,35.08) 39.24,34.91 39.01,34.91 39.01,34.9 38.77,34.66 38.42,34.66 38.3,34.78 U2.K1
  07_SIG w0.121: v4(39.87,10.18) 39.8,10.12 37.12,10.12 36.62,10.63 36.21,10.63 35.83,10.24 34.86,10.24 34.75,10.14 31.81,10.14 31.37,10.57 29.4,10.57 29.14,10.31 25.84,10.31 25.4,9.87 v4(24.75,9.87)
  08_SIG w0.121: v4(39.87,10.18) 39.61,10.18 37.95,11.84 37.95,11.85 37.9,11.91 37.9,12.55 38.78,13.43 38.78,13.8 37.95,14.62 37.95,15.72 37.65,16.03 37.65,16.92 37.23,17.34 37.02,17.34 36.76,17.6 36.76,17.96 37.02,18.22 37.05,18.22 37.91,19.08 38.52,19.08 38.78,19.34 38.78,20.02 39.04,20.28 39.71,20.28 39.72,20.27 40.09,20.27 40.43,20.61 40.43,23.34 40.25,23.52 40.25,24.28 39.99,24.54 39.99,25.23 39.84,25.37 39.84,25.73 40.1,25.99 40.38,25.99 40.69,26.3 40.69,26.5 41.14,26.95 41.14,29.88 41.2,29.94 41.2,31.57 40.61,32.15 40.61,33.31 39.8,34.13 39.8,34.15 39.41,34.54 v3(39.41,35.08)
CNTRL_SPI_SCK: length 45.1
  02_GND w0.127: U2.J2 38.35,34.28 v3(38.6,33.98)
  07_SIG w0.121: v4(23.48,9.87) 24.07,10.45 25.27,10.45 25.63,10.81 28.93,10.81 29.25,11.13 31.47,11.13 32.21,10.38 33.14,10.38 33.51,10.75 35.62,10.75 35.97,11.09 36.86,11.09 37.39,10.56 v4(38.34,10.56)
  08_SIG w0.121: v4(38.34,10.56) 38.29,10.57 37.4,11.45 37.4,15.57 37.14,15.83 37.14,16.61 37.06,16.8 37.02,16.84 36.81,16.84 36.26,17.39 36.26,18.17 36.81,18.72 36.85,18.72 37.4,19.27 37.4,19.85 37.63,20.08 37.63,20.66 38.34,21.37 38.34,21.51 38.95,22.12 39.36,22.12 39.51,22.27 39.51,23.24 39.23,23.52 39.23,24.08 39.48,24.33 39.48,26.08 40.19,26.79 40.19,31.87 40.13,31.93 40.13,32.35 40.19,32.41 40.19,32.92 39.56,33.55 39.03,33.55 v3(38.6,33.98)
CORE_FB_ALERT_L: length 20.4
  TOP w0.147: U10.2 30.76,22.47 30.64,22.6 29.78,22.6 v4(29.49,22.88)
  02_GND w0.127: v3(38.6,32.31) 38.06,32.31 37.59,32.78 U2.F2
  07_SIG w0.121: v4(29.49,22.88) 29.49,23.56 30.09,24.15 30.09,24.16 30.21,24.28 30.21,24.28 30.53,24.6 30.78,24.6 31.04,24.86 31.04,25.61 31.92,26.5 31.92,28.28 32.15,28.51 32.15,30.29 33.4,31.53 33.86,31.53 34.08,31.76 34.08,32.1 34.3,32.32 34.67,32.32 34.9,32.09 34.9,31.79 35.17,31.52 37.81,31.52 v3(38.6,32.31)
CORE_FB_FAULT_L: length 20.7
  TOP w0.127: v3(34.68,33.6) 35.1,33.13 36.1,33.13 36.84,32.39 36.84,32.34 U2.E3
  TOP w0.147: U10.3 30.88,21.97 30.53,22.32 29.82,22.32 R85.1
  07_SIG w0.121: v3(34.68,33.6) 34.34,33.94 33.71,33.94 33.48,33.71 33.48,33.26 30.48,30.26 30.48,30.24 29.58,29.34 29.58,28.09 30.15,27.52 30.15,27.15 29.96,26.96 29.96,24.48 28.94,23.47 28.94,22.5 29.44,22.01 v4(29.44,21.99)
CORE_FB_PH1_THERM_L: length 57.1
  TOP w0.147: U2.G3 36.66,33.53 v3(36.31,33.53)
  03_SIG w0.121: v3(36.31,33.53) 35.89,33.11 35.64,33.11 35.41,32.88 35.41,32.42 35.71,32.12 35.71,31.86 36.06,31.52 37.71,31.52 38.21,31.01 38.85,31.01 40.25,29.61 42.41,29.61 42.53,29.74 44.95,29.74 45.83,28.85 65.33,28.85 v2(65.9,28.28)
  04_SIG w0.121: v5(67.06,19.43) 67.06,23.12 66.41,23.77 66.41,27.77 v2(65.9,28.28)
  07_SIG w0.121: v5(67.06,19.43) 65.45,17.82 65.45,17.53 65.19,17.27 64.9,17.27 64.38,16.75 64.38,11.96 v4(65.01,11.33)
  BOTTOM w0.147: R75.1 66.9,20.83 66.9,19.96 67.06,19.8 v5(67.06,19.43) U6.38
CORE_FB_PH2_THERM_L: length 30
  02_GND w0.127: v3(38.6,33.15) 37.96,33.78 U2.H2
  07_SIG w0.121: v3(38.6,33.15) 38.75,33.15 39.14,32.75 39.57,32.75 39.67,32.85 44.33,32.85 v2(44.9,32.28)
  08_SIG w0.121: v2(44.9,32.28) 46.85,32.28 47.47,31.66 v5(47.47,19.43)
  BOTTOM w0.147: U5.38 v5(47.47,19.43) 47.47,19.8 47.3,19.96 47.3,20.83 R76.1 46.22,20.98 TP34.1
CPLD_CORE_PSI_L: length 21.6
  TOP w0.147: U10.39 32.53,24.07 32.26,24.33 31.79,24.33 31.79,24.33 31.18,24.33 31.17,24.33 30.79,24.33 30.78,24.35 29.8,24.35 29.51,24.64 v4(29.51,24.66) ; v3(33.06,33.53) 32.78,33.28 U2.G12
  07_SIG w0.121: v3(33.06,33.53) 31.56,32.03 29.96,32.03 29.69,31.76 29.69,31.14 29.2,30.64 29.2,27.07 29.51,26.76 v4(29.51,24.66)
  BOTTOM w0.147: R89.1 28.05,27.96 28.44,27.58 28.44,26.19 29.43,25.19 29.43,25.18 29.51,25.1 v4(29.51,24.66)
CPLD_GPIO_0: length 60.6
  TOP w0.127: U2.P8 33.88,37.3 33.88,38.14 v3(34.3,38.53)
  04_SIG w0.121: v3(34.3,38.53) 33.86,38.08 33.86,37.56 33.28,36.98 30.98,36.98 30.48,37.48 30.48,37.99 30.25,38.22 29.92,38.22 29.82,38.12 27.17,38.12 26.91,37.87 26.91,37.36 25.64,36.09 21.02,36.09 20.27,35.34 20.27,35.19 19.95,34.87 11.08,34.87 10.75,34.54 10.75,34.54 10.49,34.28 10.49,34.28 2.91,26.69 2.91,23.14 4.18,21.87 v4(8.88,21.87)
  BOTTOM w0.147: v4(8.88,21.87) 9.83,20.92 11.99,20.92 12.94,19.96 12.94,17.55 13.32,17.17 J5.1
CPLD_GPIO_1: length 61.8
  TOP w0.147: v3(34.68,35.18) 34.41,35.45 U2.M8
  04_SIG w0.121: v4(11.8,20.09) 11.42,20.09 9,22.5 4.18,22.5 3.29,23.39 3.29,26.06 6.91,29.68 7.28,29.68 10.15,32.55 10.15,33.17 10.59,33.62 11.1,33.62 11.54,34.06 11.54,34.31 11.77,34.54 20.72,34.54 21.83,33.42 22,33.42 22.05,33.48 22.62,33.48 22.68,33.42 25.83,33.42 28.25,35.84 29.45,35.84 29.69,35.59 29.69,35.17 29.71,35.16 29.71,35.08 29.9,34.88 30.25,34.88 30.35,34.79 34.24,34.79 34.63,35.18 v3(34.68,35.18)
  BOTTOM w0.147: J5.2 11.99,11.01 11.54,11.45 11.54,19.84 v4(11.8,20.09)
CPLD_GPIO_2: length 87.3
  TOP w0.127: U2.P3 36.91,37.22 37.24,37.54 37.24,38.24 v3(37.55,38.53)
  03_SIG w0.121: v5(22.72,34.19) 23.23,33.68 23.23,30.35 22.75,29.87 22.47,29.87 22.22,29.62 22.22,29.62 22.19,29.58 22.19,29.05 24.23,27.01 27.98,27.01 28.59,27.62 29.31,27.62 29.46,27.77 31.82,27.77 32.97,28.92 32.97,29.21 33.23,29.47 33.55,29.47 33.78,29.24 33.78,28.92 34.01,28.69 34.62,28.69 v5(35.09,28.22)
  04_SIG w0.121: v3(37.55,38.53) 37.21,38.19 37.21,37.5 36.82,37.11 36.69,37.11 35.93,36.35 30.59,36.35 30.34,36.6 27.04,36.6 24.63,34.19 v5(22.72,34.19) ; v4(10.15,20.22) 9.83,19.9 9.83,13.8 10.53,13.1 11.29,13.1 11.54,13.36 14.77,13.36 15.03,13.1 15.03,13.04 15.61,12.47 19.85,12.47 20.11,12.73 20.11,12.91 22.09,14.88 30.34,14.88 31.1,14.12 v4(31.1,13.8)
  08_SIG w0.121: v5(35.09,28.22) 34.6,27.73 34.6,27.01 32.12,24.53 32.12,20.22 31.74,19.83 31.74,17.7 31.1,17.06 v4(31.1,13.8)
CPLD_GPIO_3: length 57.5
  TOP w0.147: U2.M3 v3(36.39,35.2)
  08_SIG w0.121: v4(10.27,18.18) 13.96,14.5 13.96,12.6 16.99,9.56 22.48,9.56 23.48,10.56 30.47,10.56 31.1,9.93 v4(31.1,9.87) 33.07,9.87 34.97,11.77 34.97,13.5 34.92,13.56 34.92,13.92 34.93,13.94 34.93,19.6 35.42,20.09 35.93,20.09 36.31,20.47 36.31,23.14 37.2,24.03 37.2,25.51 37.91,26.22 37.91,26.89 38.15,27.14 38.15,28.64 37.89,28.9 37.89,29.43 37.58,29.74 37.58,33.93 36.39,35.13 v3(36.39,35.2)
CPLD_NFP_RST_LED_L: length 62.5
  02_GND w0.127: U2.F13 30.15,32.78 v3(30.09,32.79)
  08_SIG w0.121: v3(30.09,32.79) 30.5,33.2 30.5,35.53 30.25,35.78 28.88,35.78 28.44,36.22 26.53,36.22 24.63,34.31 23.16,34.31 23.16,34.37 22.9,34.63 22.54,34.63 22.28,34.37 22.28,34.31 21.2,34.31 20.56,34.95 20.56,35.72 20.19,36.09 19.57,36.09 19.14,35.65 19.14,35.17 18.78,34.82 18,34.82 17.77,34.59 17.77,33.96 17.77,33.96 17.77,32.54 17.51,32.28 13.32,32.28 13.03,32.57 13.03,34.76 12.73,35.06 12.73,35.96 12.5,36.2 11.95,36.2 11.38,36.77 11.38,36.82 9.26,38.94 9.26,49.81 9.77,50.32 9.77,58.06 v4(9.26,58.57)
  BOTTOM w0.147: v4(9.26,58.57) 9.26,58.44 8.75,57.94 8.75,56.82 7.35,55.43 7.35,55.4 v1(6.72,54.76) 7.23,54.25 7.7,54.25 R276.1
CPLD_NIC_MEZZ_ID0: length 41
  02_GND w0.127: U2.N12 32.41,37.5 v3(32.63,37.72)
  04_SIG w0.121: v3(32.63,37.72) 32.22,38.12 31.61,38.12 30.98,38.76 26.28,38.76 25.64,38.12 25.64,37.36 24.88,36.6 23.23,36.6 22.59,37.23 22.59,39.39 23.36,40.16 23.36,41.68 23.56,41.88 23.56,41.91 23.66,42.02 23.66,42.77 22.79,43.65 22.79,47.58 v6(21.83,48.54)
  07_SIG w0.121: v5(19.55,57.01) 20.43,56.12 20.43,50.06 20.77,49.73 20.77,49.6 v6(21.83,48.54)
  BOTTOM w0.147: J4.5 15.38,55.93 15.74,56.28 18.82,56.28 v5(19.55,57.01)
CPLD_NIC_MEZZ_ID1: length 27
  TOP w0.127: v3(35.5,33.55) 35.89,33.95 36.74,33.95 U2.H3
  TOP w0.147: R395.2 20.14,34.86 20.07,34.79 17.97,34.79 v6(17.28,34.1)
  04_SIG w0.121: v3(35.5,33.55) 35.13,33.18 34.05,33.18 34.01,33.13 32.9,33.13 32.85,33.18 31.6,33.18 30.72,34.06 29.96,34.06 29.69,34.32 29.69,34.71 29.46,34.94 29.11,34.94 29.1,34.95 27.93,34.95 26.15,33.17 22.58,33.17 22.52,33.23 22.16,33.23 22.1,33.17 21.45,33.17 20.96,33.66 17.73,33.66 v6(17.28,34.1)
  BOTTOM w0.254: J4.139 v6(17.28,34.1)
CPLD_PCIE0_WAKE_L: length 49.6
  TOP w0.127: v3(36.82,37.72) 36.82,37.6 36.41,37.19 U2.P4
  TOP w0.147: R367.1 v5(13.32,58.57)
  04_SIG w0.121: v3(36.82,37.72) 35.7,36.6 31.05,36.6 30.21,37.44 29.92,37.44 29.88,37.49 28.44,37.49 27.93,36.98 27.04,36.98 24.88,34.82 23.61,34.82 v5(22.85,35.58)
  07_SIG w0.121: v6(21.7,45.36) 21.7,45.74 20.18,47.27 14.85,47.27 14.08,48.03 14.08,49.68 13.58,50.19 13.58,52.47 14.08,52.98 14.08,57.05 13.32,57.81 v5(13.32,58.57)
  08_SIG w0.121: v5(22.85,35.58) 22.53,35.9 22.53,43.01 22.59,43.07 22.59,44.47 v6(21.7,45.36)
  BOTTOM w0.147: v3(36.82,37.72) 36.66,37.72 36.4,37.45 R397.2
CPLD_PGRM_JTAG_SEL: length 36.7
  TOP w0.132: U1.AB27 v2(46.9,46.28)
  TOP w0.147: v4(28.69,29.07) 28.31,28.69 28.31,26.44 28.05,26.18 U12.1
  04_SIG w0.121: v2(46.9,46.28) 46.9,45.92 46.47,45.49 46.47,43.28 46.07,42.88 45.89,42.88 45.33,42.31 45.33,42.14 45.07,41.88 44.93,41.88 44.31,41.26 44.31,36.09 44.06,35.84 40.25,35.84 40.12,35.96 39.99,35.96 39.68,36.28 39.23,36.28 38.71,35.76 37.25,35.76 36.78,35.29 36.78,32.05 34.6,29.87 29.49,29.87 v4(28.69,29.07)
CPLD_PGRM_JTAG_TCK: length 14.8
  TOP w0.147: U12.4 26.02,27.97 25.26,28.73 v4(25.26,29.07)
  02_GND w0.121: U2.B6 35.41,30.26 v3(34.23,29.08)
  03_SIG w0.121: v4(25.26,29.07) 25.26,28.85 25.9,28.22 25.92,28.22 26.01,28.13 29.1,28.13 30.68,29.7 33.64,29.7 34.23,29.11 v3(34.23,29.08)
CPLD_PGRM_JTAG_TDI: length 23.4
  TOP w0.147: U12.7 24.52,27.31 23.23,28.6 23.23,29.12 22.99,29.36 v4(22.63,29.36)
  02_GND w0.121: U2.B4 36.41,29.36 36.69,29.08 v3(36.69,28.47)
  03_SIG w0.121: v4(22.63,29.36) 22.8,29.49 25.06,29.49 25.08,29.51 25.49,29.51 25.96,29.04 25.96,28.89 26.22,28.63 28.97,28.63 30.34,30 35.78,30 36.69,29.08 v3(36.69,28.47)
  BOTTOM w0.147: R159.1 36.56,29.21 36.69,29.08 v3(36.69,28.47)
CPLD_PGRM_JTAG_TDO: length 19.6
  TOP w0.147: R62.2 24.07,24.27 U12.9
  03_SIG w0.121: v4(23.25,23.58) 24.88,25.17 30.1,25.17 30.41,25.48 31.29,25.48 32.82,27.01 32.82,27.77 33.39,28.33 v3(33.39,29.08)
  BOTTOM w0.147: v3(33.39,29.08) 34.3,30 34.4,30 35.08,30.67 R264.2 R159.2
CPLD_PGRM_JTAG_TMS: length 16
  TOP w0.127: 33.81,28.69 33.81,29.26 34.29,29.74 34.91,29.74 35.41,30.24 U2.A6
  TOP w0.147: R61.2 25.52,24.06 U12.12 ; 33.81,28.69 v3(34.23,28.27)
  03_SIG w0.121: v3(34.23,28.27) 33.7,27.74 33.7,27.14 33.9,26.95 33.9,26.19 31.86,24.15 26.53,24.15 26.02,23.65 v4(26.02,23.58)
CPLD_SMBUS_ALERT_L: length 69.5
  TOP w0.147: 20.8,53.73 20.8,52.97 20.56,52.73 R392.1 ; 20.8,53.73 v1(20.82,53.74) ; 20.8,53.73 19.58,53.73 19.47,53.62 17.64,53.62 17.53,53.73 17.04,53.73 16.92,53.6 14.22,53.6 14.2,53.62 10.53,53.62 9.76,54.39 9.76,55.29 9.51,55.54 7.97,55.54 7.7,55.81 v5(7.7,56.41)
  02_GND w0.127: v3(30.09,35.33) 30.43,34.99 31.14,34.99 31.36,34.78 U2.K13
  08_SIG w0.121: v3(30.09,35.33) 29.64,34.88 28.5,34.88 27.55,35.84 26.66,35.84 24.75,33.93 23.09,33.93 22.9,33.75 22.54,33.75 22.35,33.93 20.94,33.93 20.31,34.57 20.31,35.58 20.05,35.84 19.67,35.84 19.38,35.55 19.38,35.04 18.91,34.57 18.28,34.57 18.02,34.31 18.02,32.38 17.64,32 12.97,32 12.69,32.28 12.69,34.24 12.39,34.54 11.95,34.54 11.54,34.95 11.14,34.95 11.12,34.93 10.42,34.93 9.77,35.58 9.77,36.98 9,37.74 9,46.76 8.24,47.52 8.24,55.9 7.73,56.41 v5(7.7,56.41)
CPLD_SMBUS_SCL: length 48.5
  TOP w0.127: U2.P7 34.72,36.96 34.72,37.89 35.11,38.28 v3(35.12,38.53)
  TOP w0.147: R390.1 18.78,58.44 v5(18.66,58.57)
  04_SIG w0.121: v3(35.12,38.53) 35.12,38.94 34.79,39.27 26.15,39.27 24.5,37.62 24.5,37.5 24.05,37.05 23.66,37.05 23.36,37.36 23.36,37.74 24.06,38.44 24.06,41.7 24.08,41.73 24.08,42.14 24.06,42.16 24.06,43.08 23.71,43.43 v5(23.71,47.52)
  07_SIG w0.121: v5(18.66,58.57) 18.66,56.67 19.16,56.16 19.16,50.19 19.57,49.78 20.01,49.78 20.27,49.52 20.27,49.21 21.45,48.03 23.2,48.03 v5(23.71,47.52)
  BOTTOM w0.147: v5(23.71,47.52) 24.63,47.52 v1(25.13,48.03) ; v5(18.66,58.57) 19.67,57.55 22.34,57.55 23.23,56.67 R399.2
CPLD_SMBUS_SDA: length 32.1
  TOP w0.147: R350.1 20.82,44.98 v6(21.7,44.09)
  02_GND w0.127: U2.N6 35.14,36.54 v3(35.14,37.72)
  04_SIG w0.121: v6(21.7,44.09) 23.42,42.51 23.42,42.12 23.03,41.74 23.03,40.22 22.34,39.52 22.34,36.98 22.97,36.35 25.13,36.35 25.96,37.17 25.96,37.94 26.53,38.5 30.72,38.5 31.36,37.87 31.36,37.49 31.61,37.23 32.75,37.23 33.07,37.55 33.07,38.69 33.3,38.92 34.49,38.92 34.72,38.69 34.72,38.13 v3(35.14,37.72)
  BOTTOM w0.147: v3(35.14,37.72) 35.19,37.72 35.81,37.1 35.81,36.24 35.96,36.09 R398.2
CPLD_VERSION_0: length 5.7
  02_GND w0.127: U2.N8 34.41,37.11 34.3,37.21 v3(34.3,37.72)
  BOTTOM w0.127: v3(34.3,37.72) 35,37.02 R49.1 35.08,36.98 35.42,36.98 35.55,36.85 35.55,36.09 35.58,36.09 36.05,35.62 36.62,35.62 R50.2
CPLD_VERSION_1: length 2.9
  TOP w0.147: U2.M9 33.91,35.21 v3(33.87,35.18)
  BOTTOM w0.127: v3(33.87,35.18) 33.9,35.2 R55.1 33.06,37.02 R52.2
CPLD_VERSION_2: length 6.5
  02_GND w0.127: v3(33.46,37.72) 33.46,37.22 33.41,37.17 U2.N10
  BOTTOM w0.127: 33.05,38.14 33.05,39.36 v1(32.92,39.48) R54.1 ; 33.05,38.14 32.45,38.14 32.21,37.89 32.21,37.54 31.99,37.33 R53.2 ; 33.05,38.14 v3(33.46,37.72)
DDR0_32A_A0: length 66.9
  TOP w0.147: V3_A-A00.1 85.01,32.38 R206.1
  TOP w0.234: v2(65.9,47.28) U1.AD8
  04_SIG w0.121: V3_A-A00.1 84.62,33.41 84.62,44.17 V2_A-A00.1 84.62,44.96 84.62,55.73 V1_A-A00.1
  07_SIG w0.121: 85.41,58.44 85.41,56.76 85.01,56.37 V1_A-A00.1
  07_SIG w0.189: v2(65.9,47.28) 66.39,47.78 68.19,47.78 68.4,47.99 68.4,48.5 68.69,48.79 69.08,48.79 69.46,49.17 69.46,54.38 68.29,55.55 68.29,59.84 68.48,60.03 68.81,60.03 68.83,60.04 86.86,60.04 87.06,59.84 87.06,58.84 86.86,58.63 85.6,58.63 85.41,58.44
  BOTTOM w0.147: U18.N3 V2_A-A00.1 ; U19.N3 V3_A-A00.1 ; U17.N3 V1_A-A00.1
DDR0_32A_A1: length 67.1
  TOP w0.147: R207.1 85.81,29.55 V3_A-A01.1
  TOP w0.234: v8(67.9,39.28) U1.T7
  04_SIG w0.121: V1_A-A01.1 86.21,51.73 86.21,40.96 V2_A-A01.1 86.21,40.17 86.21,29.41 V3_A-A01.1
  08_SIG w0.121: V1_A-A01.1 85.81,51.88 86.22,51.48 86.22,50.09
  08_SIG w0.189: v8(67.9,39.28) 67.9,40.61 68.08,40.79 74.07,40.79 74.35,41.07 74.35,41.81 74.37,41.82 74.37,42.21 74.38,42.22 74.38,42.29 74.79,42.7 78.04,42.7 78.4,42.34 78.4,41.98 78.57,41.81 89.12,41.81 89.34,42.04 89.34,50.87 89.19,51.03 88.39,51.03 88.23,50.86 88.23,50.13 88.08,49.99 86.32,49.99 86.22,50.09
  BOTTOM w0.147: U18.P7 V2_A-A01.1 ; U17.P7 V1_A-A01.1 ; U19.P7 V3_A-A01.1
DDR0_32A_A2: length 67.2
  TOP w0.147: R208.1 85.81,32.47 V3_A-A02.1
  TOP w0.234: v2(65.9,48.28) U1.AD9
  04_SIG w0.121: V3_A-A02.1 85.42,33.41 85.42,44.17 V2_A-A02.1 85.42,44.96 85.42,55.73 V1_A-A02.1
  07_SIG w0.121: 86.21,58.08 86.21,56.76 85.97,56.53 85.97,56.28 V1_A-A02.1
  07_SIG w0.189: v2(65.9,48.28) 67.17,48.28 67.68,48.79 68.06,48.79 68.44,49.17 68.44,54.56 67.71,55.29 67.71,58.93 67.14,59.5 67.14,60.25 67.32,60.43 68.65,60.43 68.66,60.44 87.28,60.44 87.45,60.26 87.45,58.54 87.24,58.32 86.45,58.32 86.21,58.08
  BOTTOM w0.147: U18.P3 V2_A-A02.1 ; U17.P3 V1_A-A02.1 ; U19.P3 V3_A-A02.1
DDR0_32A_A3: length 69.4
  TOP w0.147: V3_A-A03.1 85.4,34.2 85.4,35.02 85.71,35.33 R209.1
  TOP w0.234: v8(66.9,39.28) U1.T8
  07_SIG w0.121: V1_A-A03.1 84.85,56.77 84.85,56.66 84.62,56.42 84.62,45.76 V2_A-A03.1 84.62,44.97 84.62,34.21 V3_A-A03.1
  08_SIG w0.121: V1_A-A03.1 84.62,56.53 84.62,55.83
  08_SIG w0.189: v8(66.9,39.28) 66.9,39.41 65.39,40.92 65.39,48.39 65.46,48.46 65.46,48.46 65.72,48.72 65.95,48.72 66.07,48.85 66.08,48.85 66.34,49.1 66.34,49.11 66.46,49.23 66.46,49.46 66.72,49.72 67.08,49.72 69.2,51.84 71.11,51.84 71.36,52.09 71.36,53.74 72.73,55.12 73.11,55.12 73.95,55.95 73.95,57.63 74.09,57.77 74.71,57.77 74.89,57.59 74.89,55.17 75.17,54.89 77.18,54.89 77.44,55.15 77.44,55.5 77.64,55.7 78.17,55.7 78.98,54.89 79.69,54.89 79.87,55.07 79.87,55.37 80.05,55.55 80.43,55.55 80.76,55.88 80.76,56.18 80.88,56.31 81.21,56.31 81.34,56.18 81.34,55.75 81.44,55.65 84.44,55.65 84.62,55.83
  BOTTOM w0.147: U19.N2 V3_A-A03.1 ; U17.N2 V1_A-A03.1 ; U18.N2 V2_A-A03.1
DDR0_32A_A4: length 68.2
  TOP w0.147: V3_A-A04.1 86.24,27.78 86.24,26.94 R210.1
  TOP w0.234: v2(66.9,47.28) U1.AC8
  03_SIG w0.121: V1_A-A04.1 86.21,50.93 86.21,40.17 V2_A-A04.1 86.21,39.37 86.21,28.61 V3_A-A04.1
  08_SIG w0.121: 85.41,52.47 85.41,51.84 85.81,51.43 V1_A-A04.1
  08_SIG w0.189: v2(66.9,47.28) 67.4,47.78 69.2,47.78 69.38,47.96 69.38,48.54 69.62,48.78 74.02,48.78 74.34,49.1 74.34,49.83 74.41,49.9 74.41,53.36 74.79,53.74 80.99,53.74 81.19,53.95 81.19,54.33 81.39,54.53 84.92,54.53 85.28,54.89 87.71,54.89 87.72,54.9 88.13,54.9 88.16,54.92 88.34,54.92 88.58,55.17 88.58,55.35 88.59,55.36 88.59,57.18 88.86,57.45 89.18,57.45 89.37,57.26 89.37,56.84 89.38,56.83 89.38,54.04 88.75,53.4 87.73,53.4 87.71,53.43 86.36,53.43 85.41,52.47
  BOTTOM w0.147: U18.P8 V2_A-A04.1 ; U17.P8 V1_A-A04.1 ; U19.P8 V3_A-A04.1
DDR0_32A_A5: length 68.8
  TOP w0.147: V3_A-A05.1 86.24,34.24 86.8,34.24 87.04,34.48 87.04,35.1 R211.1
  TOP w0.234: v8(65.9,39.28) U1.T9
  07_SIG w0.121: V3_A-A05.1 85.42,34.21 85.42,44.97 V2_A-A05.1 85.42,45.76 85.42,56.42 85.65,56.66 85.65,56.77 V1_A-A05.1
  08_SIG w0.121: V1_A-A05.1 85.41,57.33 85.41,57.99 85.33,58.06
  08_SIG w0.189: v8(65.9,39.28) 65.9,39.7 65.7,39.9 64.71,39.9 64.38,40.23 64.38,48.54 64.68,48.85 65.08,48.85 65.34,49.1 65.34,49.12 65.46,49.24 65.46,49.46 65.47,49.47 65.47,49.65 65.66,49.85 66.08,49.85 66.09,49.85 66.22,49.85 66.41,50.04 66.41,50.62 66.85,51.07 66.85,51.4 67.92,52.46 70.28,52.46 70.47,52.66 70.47,53.09 70.46,53.1 70.46,54.46 70.47,54.47 70.47,54.54 70.65,54.71 70.71,54.71 70.72,54.72 71.08,54.72 71.09,54.71 71.29,54.71 71.46,54.89 71.46,55.46 71.49,55.49 71.49,55.62 71.67,55.8 73.27,55.8 73.52,56.06 73.52,57.91 73.79,58.18 74.44,58.18 74.46,58.19 85.19,58.19 85.25,58.13 85.27,58.13 85.33,58.06
  BOTTOM w0.147: U19.P2 V3_A-A05.1 ; U17.P2 V1_A-A05.1 ; U18.P2 V2_A-A05.1
DDR0_32A_A6: length 68.3
  TOP w0.147: R212.1 87.1,26.91 87.1,27.59 86.61,28.08 V3_A-A06.1
  TOP w0.234: v8(67.9,48.28) U1.AD7
  03_SIG w0.121: V1_A-A06.1 87.01,50.93 87.01,40.17 V2_A-A06.1 87.01,39.37 87.01,28.61 V3_A-A06.1
  08_SIG w0.121: V1_A-A06.1 86.61,51.57 86.22,51.96 86.22,52.7
  08_SIG w0.189: 86.22,52.7 86.63,53.11 87.58,53.11 87.6,53.08 87.67,53.08 87.75,53.01 88.91,53.01 89.01,53.11 89.43,53.11 89.77,53.45 89.77,53.87 89.78,53.88 89.78,56.99 89.77,57 89.77,58.05 89.62,58.19 88.35,58.19 88.2,58.04 88.2,55.52 87.97,55.29 85.15,55.29 84.77,54.91 81.01,54.91 80.84,54.74 80.84,54.3 80.66,54.13 74.41,54.13 74.03,53.74 73.65,53.74 73.4,53.5 73.4,50.07 73.11,49.78 68.72,49.78 68.41,49.48 68.41,48.8 v8(67.9,48.28)
  BOTTOM w0.147: U19.R8 V3_A-A06.1 ; U17.R8 V1_A-A06.1 ; U18.R8 V2_A-A06.1
DDR0_32A_A7: length 69.7
  TOP w0.147: R213.1 87.66,35.42 88,35.08 88,34.57 87.67,34.24 87.22,34.24 86.79,33.81 V3_A-A07.1
  TOP w0.234: v8(65.9,38.28) U1.R9
  07_SIG w0.121: V3_A-A07.1 86.22,34.21 86.22,44.97 V2_A-A07.1 86.22,45.76 86.22,56.42 86.45,56.66 86.45,56.77 V1_A-A07.1
  08_SIG w0.121: 86.22,58.19 86.22,58.19 86.22,57.32 V1_A-A07.1
  08_SIG w0.189: 86.22,58.19 86.22,58.19 85.97,58.44 85.38,58.44 85.25,58.57 73.58,58.57 71.73,56.72 71.72,56.72 71.46,56.46 71.46,56.46 71.34,56.33 71.34,56.1 71.08,55.85 70.79,55.85 66.34,51.39 66.34,51.1 66.08,50.85 65.79,50.85 65.39,50.44 65.39,50.19 65.34,50.13 65.34,50.1 65.08,49.85 64.79,49.85 64.34,49.39 64.34,49.1 64.08,48.85 63.85,48.85 63.73,48.72 63.72,48.72 63.46,48.46 63.46,40.44 64.38,39.52 64.38,39.17 65.27,38.28 v8(65.9,38.28)
  BOTTOM w0.147: U18.R2 V2_A-A07.1 ; U19.R2 V3_A-A07.1 ; U17.R2 V1_A-A07.1
DDR0_32A_A8: length 68.4
  TOP w0.147: R214.1 87.94,26.86 87.94,27.68 V3_A-A08.1
  TOP w0.234: v2(67.9,49.28) U1.AE7
  03_SIG w0.121: V1_A-A08.1 87.81,50.93 87.81,40.17 V2_A-A08.1 87.87,39.31 87.87,28.67 V3_A-A08.1
  08_SIG w0.121: 87.01,52.42 87.01,51.97 87.41,51.57 V1_A-A08.1
  08_SIG w0.189: v2(67.9,49.28) 67.9,50 68.68,50.78 72.22,50.78 72.4,50.96 72.4,53.67 72.57,53.85 73.08,53.85 73.34,54.1 73.34,54.54 73.55,54.76 74.54,54.76 74.79,54.51 77.25,54.51 77.33,54.58 78.6,54.58 78.68,54.51 80.23,54.51 80.48,54.76 80.48,55.12 80.66,55.29 84.62,55.29 84.98,55.65 87.62,55.65 87.87,55.9 87.87,58.39 88.07,58.6 89.98,58.6 90.16,58.42 90.16,57.16 90.17,57.15 90.17,53.71 90.16,53.7 90.16,53.29 89.47,52.6 87.19,52.6 87.01,52.42
  BOTTOM w0.147: U19.T8 V3_A-A08.1 ; U17.T8 V1_A-A08.1 ; U18.T8 V2_A-A08.1
DDR0_32A_A9: length 67.3
  TOP w0.147: R215.1 86.61,32.56 V3_A-A09.1
  TOP w0.234: v8(68.9,49.28) U1.AE6
  03_SIG w0.189: v8(68.9,49.28) 69.4,49.78 69.4,55.47 72.08,58.15 75.23,58.15 75.24,58.15 80.39,58.15 80.4,58.15 80.85,58.15 81.04,57.96 81.04,54.43 80.84,54.23 80.23,54.23 80,54.46 80,54.58 79.69,54.89 78.46,54.89 78.15,54.58 77.66,54.58 77.48,54.41 77.48,52.83 77.71,52.6 81.01,52.6 82.05,53.64 84.8,53.64 84.98,53.82 84.98,55.47 85.15,55.65 86.44,55.65 86.61,55.83 V1_A-A09.1
  07_SIG w0.121: V1_A-A09.1 87.01,55.73 87.01,44.96 V2_A-A09.1 87.01,44.17 87.01,33.41 V3_A-A09.1
  BOTTOM w0.147: U18.R3 V2_A-A09.1 ; U17.R3 V1_A-A09.1 ; U19.R3 V3_A-A09.1
DDR0_32A_A10: length 67
  TOP w0.147: V3_A-A10.1 83.3,29.13 R216.1
  TOP w0.234: v2(67.9,44.28) U1.Y7
  03_SIG w0.121: V1_A-A10.1 83.81,51.73 83.81,40.96 V2_A-A10.1 83.81,40.17 83.81,29.41 V3_A-A10.1
  08_SIG w0.121: V1_A-A10.1 83.82,51.72 83.82,50.06
  08_SIG w0.189: v2(67.9,44.28) 68.4,43.78 74.8,43.78 74.98,43.6 74.98,43.59 75.24,43.34 76.39,43.34 76.41,43.36 78.46,43.36 78.49,43.33 78.68,43.33 79.06,42.95 79.06,42.8 79.26,42.59 81.44,42.59 81.7,42.85 81.7,43.03 81.95,43.28 82.49,43.28 82.66,43.1 82.66,42.85 82.92,42.59 88.38,42.59 88.51,42.72 88.51,48.84 88.33,49.02 87.34,49.02 87.19,48.87 87.19,47.12 87.03,46.96 85.13,46.96 84.98,47.12 84.98,49.43 84.82,49.58 84.01,49.58 83.82,49.77 83.82,50.06
  BOTTOM w0.147: U18.L7 V2_A-A10.1 ; U19.L7 V3_A-A10.1 ; U17.L7 V1_A-A10.1
DDR0_32A_A11: length 67.2
  TOP w0.147: R217.1 86.61,29.46 V3_A-A11.1
  TOP w0.234: v8(66.9,38.28) U1.R8
  04_SIG w0.121: V3_A-A11.1 87.01,29.41 87.01,40.17 V2_A-A11.1 87.01,40.96 87.01,51.73 V1_A-A11.1
  08_SIG w0.121: V1_A-A11.1 86.61,51.92 87.01,51.52 87.01,51.1 87.19,50.93 87.64,50.93
  08_SIG w0.189: v8(66.9,38.28) 66.95,38.28 67.42,38.76 68.06,38.76 68.4,39.1 68.4,39.99 68.69,40.28 74.08,40.28 74.67,40.87 74.67,41.68 74.69,41.69 74.69,42.08 74.92,42.31 77.51,42.31 77.97,41.86 77.97,41.6 78.14,41.43 87.73,41.43 87.75,41.41 89.28,41.41 89.29,41.43 89.57,41.43 89.71,41.57 89.71,41.85 89.74,41.87 89.74,51.04 89.71,51.06 89.71,51.24 89.5,51.46 88.18,51.46 87.64,50.93
  BOTTOM w0.147: U17.R7 V1_A-A11.1 ; U18.R7 V2_A-A11.1 ; U19.R7 V3_A-A11.1
